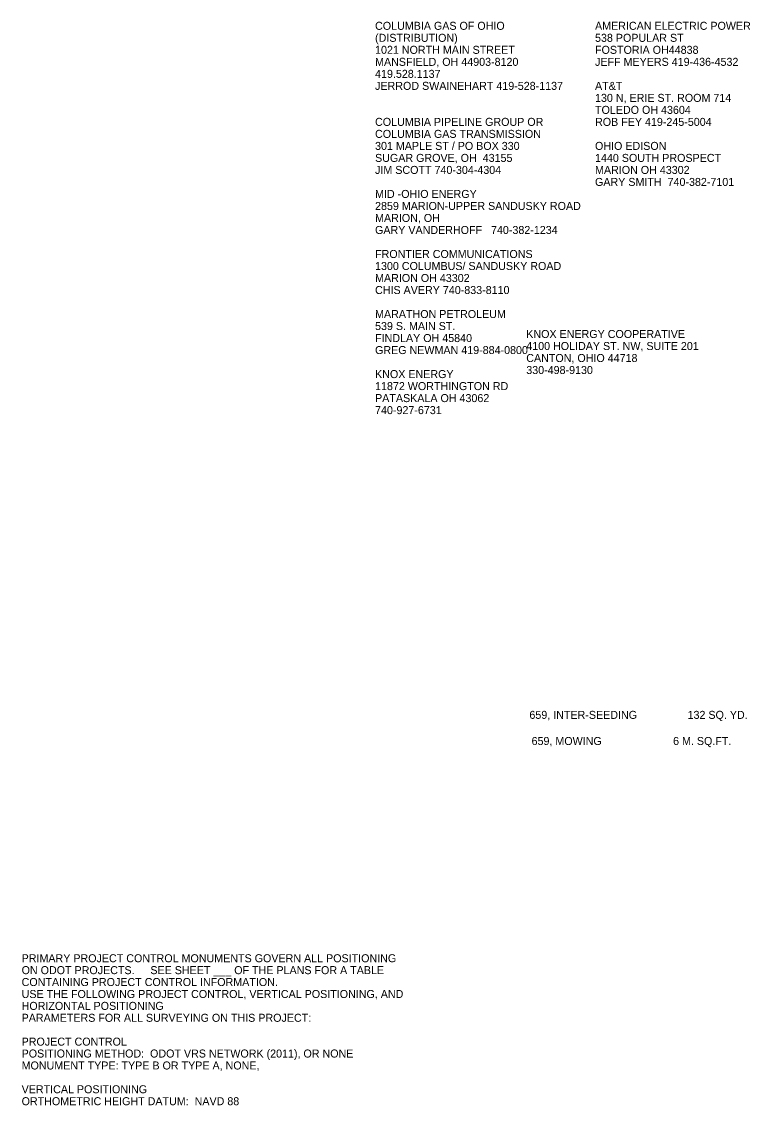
# Model space of a CAD drawing. Extents: x -14.3 to 49.6, y -18.9 to 35.3.
# Drawn here: x -14.33 to -1.59, y 0.03 to 18.98 of the extents above; entities that cross this region are included whole.
import ezdxf

# ---------------------------------------------------------------- set-up
doc = ezdxf.new("R2010")
doc.units = 0
doc.layers.add('SH_Text', color=7, linetype='Continuous')

msp = doc.modelspace()

# ---------------------------------------------------------------- texts
at = {"layer": 'SH_Text'}
for s, p in [('COLUMBIA GAS OF OHIO', (-8.151, 18.84)), ('AMERICAN ELECTRIC POWER', (-4.303, 18.84)), ('(DISTRIBUTION)', (-8.151, 18.63)), ('538 POPULAR ST', (-4.303, 18.63)), ('1021 NORTH MAIN STREET', (-8.151, 18.42)), ('FOSTORIA OH44838', (-4.303, 18.42)), ('MANSFIELD, OH 44903-8120', (-8.151, 18.21)), ('JEFF MEYERS 419-436-4532', (-4.303, 18.21)), ('419.528.1137', (-8.151, 18)), ('JERROD SWAINEHART 419-528-1137', (-8.151, 17.79)), ('AT&T', (-4.303, 17.79)), ('130 N, ERIE ST. ROOM 714', (-4.303, 17.58)), ('TOLEDO OH 43604', (-4.303, 17.37)), ('COLUMBIA PIPELINE GROUP OR', (-8.151, 17.16)), ('ROB FEY 419-245-5004', (-4.303, 17.16)), ('COLUMBIA GAS TRANSMISSION', (-8.151, 16.95)), ('301 MAPLE ST / PO BOX 330', (-8.151, 16.74)), ('OHIO EDISON', (-4.303, 16.74)), ('SUGAR GROVE, OH  43155', (-8.151, 16.53)), ('1440 SOUTH PROSPECT', (-4.303, 16.53)), ('JIM SCOTT 740-304-4304', (-8.151, 16.32)), ('MARION OH 43302', (-4.303, 16.32)), ('GARY SMITH  740-382-7101', (-4.303, 16.11)), ('MID -OHIO ENERGY', (-8.151, 15.9)), ('2859 MARION-UPPER SANDUSKY ROAD', (-8.151, 15.69)), ('MARION, OH ', (-8.151, 15.48)), ('GARY VANDERHOFF   740-382-1234', (-8.151, 15.27)), ('FRONTIER COMMUNICATIONS', (-8.151, 14.85)), ('1300 COLUMBUS/ SANDUSKY ROAD', (-8.151, 14.64)), ('MARION OH 43302', (-8.151, 14.43)), ('CHIS AVERY 740-833-8110', (-8.151, 14.22)), ('MARATHON PETROLEUM ', (-8.151, 13.8)), ('539 S. MAIN ST.', (-8.151, 13.59)), ('FINDLAY OH 45840', (-8.151, 13.38)), ('KNOX ENERGY COOPERATIVE', (-5.506, 13.451)), ('GREG NEWMAN 419-884-0800', (-8.151, 13.17)), ('4100 HOLIDAY ST. NW, SUITE 201', (-5.506, 13.241)), ('CANTON, OHIO 44718', (-5.506, 13.031)), ('KNOX ENERGY ', (-8.151, 12.75)), ('330-498-9130', (-5.506, 12.821)), ('11872 WORTHINGTON RD', (-8.151, 12.54)), ('PATASKALA OH 43062', (-8.151, 12.33)), ('740-927-6731', (-8.151, 12.12)), ('659, INTER-SEEDING                 132 SQ. YD.', (-5.451, 6.791)), ('659, MOWING                        6 M. SQ.FT.', (-5.413, 6.334)), ('PRIMARY PROJECT CONTROL MONUMENTS GOVERN ALL POSITIONING ', (-14.334, 2.535)), ('ON ODOT PROJECTS. ', (-14.334, 2.327)), ('SEE SHEET ___ OF THE PLANS FOR A TABLE ', (-12.082, 2.327)), ('CONTAINING PROJECT CONTROL INFORMATION. ', (-14.334, 2.119)), ('USE THE FOLLOWING PROJECT CONTROL, VERTICAL POSITIONING, AND ', (-14.334, 1.91)), ('HORIZONTAL POSITIONING', (-14.334, 1.702)), ('PARAMETERS FOR ALL SURVEYING ON THIS PROJECT:', (-14.334, 1.494)), ('PROJECT CONTROL', (-14.334, 1.077)), ('POSITIONING METHOD:  ODOT VRS NETWORK (2011), OR NONE', (-14.334, 0.869)), ('MONUMENT TYPE: TYPE B OR TYPE A, NONE, ', (-14.334, 0.66)), ('VERTICAL POSITIONING', (-14.334, 0.244)), ('ORTHOMETRIC HEIGHT DATUM:  NAVD 88', (-14.334, 0.035))]:
    msp.add_text(s, height=0.14, dxfattribs=at).set_placement(p)

doc.saveas('drawing.dxf')
